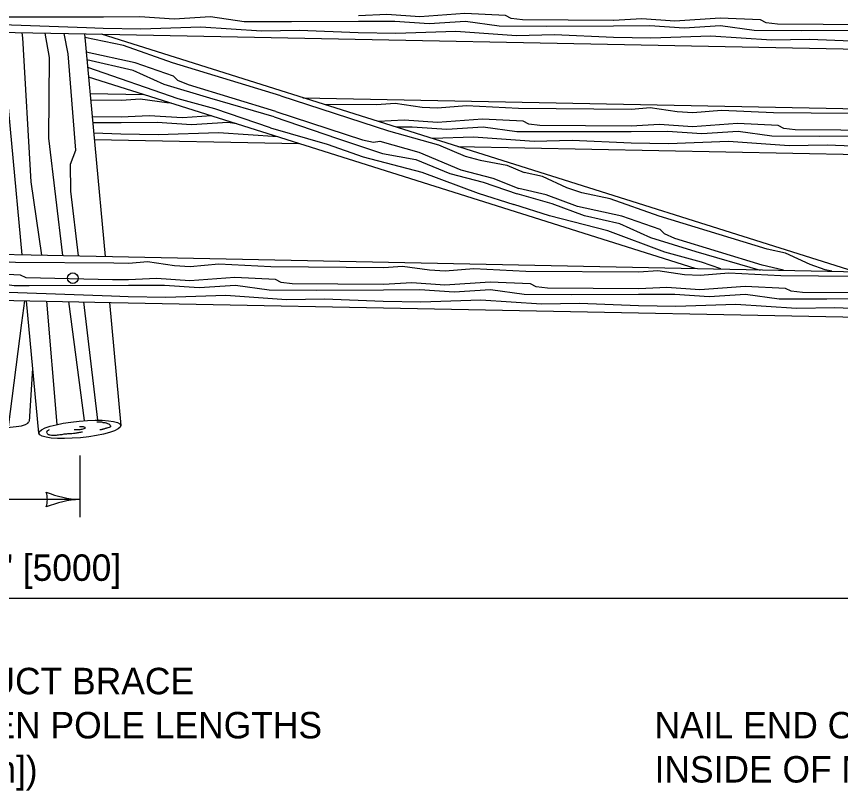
# Model space of a CAD drawing. Extents: x 49991.4 to 50021, y 49987.6 to 50011.4.
# Drawn here: x 50012.08 to 50013.947, y 49990.172 to 49991.926 of the extents above; entities that cross this region are included whole.
import ezdxf

# ---------------------------------------------------------------- set-up
doc = ezdxf.new("R2010")
doc.units = 0
for name, color, linetype in [('Level 1', 7, 'Continuous'), ('Level 2', 7, 'Continuous'), ('Level 3', 7, 'Continuous')]:
    doc.layers.add(name, color=color, linetype=linetype)

msp = doc.modelspace()

# ---------------------------------------------------------------- linework, layer by layer
at = {"layer": 'Level 1'}
for p, q in [((50009.7667, 49991.9345), (50012.238, 49991.8861)), ((50012.0454, 49991.8899), (50012.0923, 49991.3859)), ((50012.2344, 49991.8862), (50012.2813, 49991.3821)), ((50012.238, 49991.8861), (50014.3555, 49991.8446)), ((50013.9784, 49991.3477), (50012.273, 49991.8854)), ((50013.6177, 49991.355), (50012.2435, 49991.7883)), ((50012.2469, 49991.7514), (50012.3683, 49991.749)), ((50012.7289, 49991.7417), (50014.2392, 49991.7111)), ((50012.2566, 49991.6471), (50012.7202, 49991.638)), ((50013.0799, 49991.631), (50014.2673, 49991.6077)), ((50009.8311, 49991.4318), (50012.1135, 49991.3855)), ((50012.1135, 49991.3855), (50014.4188, 49991.3388)), ((50009.8234, 49991.3261), (50012.2947, 49991.2777)), ((50012.1021, 49991.2815), (50012.13, 49990.9817)), ((50012.291, 49991.2778), (50012.3169, 49990.999)), ((50012.2947, 49991.2777), (50014.4122, 49991.2362)), ((50012.1163, 49991.128), (50012.1087, 49991.0076))]:
    msp.add_line(p, q, dxfattribs=at)
for points in [[(50012.2773, 49991.9243), (50012.0522, 49991.9239)], [(50012.8552, 49991.9142), (50012.7035, 49991.9134), (50012.5958, 49991.914), (50012.5195, 49991.9246), (50012.4371, 49991.9194), (50012.3593, 49991.9246), (50012.2773, 49991.9243)], [(50013.4334, 49991.9168), (50013.2264, 49991.9185), (50013.201, 49991.9215), (50013.1883, 49991.9281), (50013.0964, 49991.9324), (50012.9941, 49991.9251), (50012.919, 49991.9302), (50012.8554, 49991.9269)], [(50012.2389, 49991.9), (50011.9199, 49991.9117), (50011.7837, 49991.9071), (50011.6989, 49991.9086)], [(50013.4331, 49991.9041), (50013.2814, 49991.9034), (50013.1737, 49991.904), (50013.0974, 49991.9145), (50013.0151, 49991.9093), (50012.9372, 49991.9145), (50012.8552, 49991.9142)], [(50014.011, 49991.8941), (50013.8594, 49991.8933), (50013.7516, 49991.8939), (50013.6754, 49991.9045), (50013.593, 49991.8992), (50013.5151, 49991.9045), (50013.4331, 49991.9041)], [(50014.0113, 49991.9068), (50013.8043, 49991.9084), (50013.7789, 49991.9114), (50013.7662, 49991.9181), (50013.6743, 49991.9223), (50013.572, 49991.915), (50013.497, 49991.9202), (50013.4333, 49991.9168)], [(50012.1376, 49991.385), (50012.1135, 49991.5509), (50012.0947, 49991.8774), (50012.0928, 49991.889)], [(50012.1853, 49991.3841), (50012.1532, 49991.65), (50012.1553, 49991.833), (50012.1448, 49991.8879)], [(50012.2204, 49991.3833), (50012.203, 49991.5302), (50012.2025, 49991.5911), (50012.2144, 49991.6228), (50012.1971, 49991.8408), (50012.1879, 49991.8871)], [(50012.2768, 49991.8985), (50012.2389, 49991.9)], [(50012.8547, 49991.8884), (50012.7216, 49991.8939), (50012.6351, 49991.8922), (50012.4978, 49991.9016), (50012.3616, 49991.897), (50012.2768, 49991.8985)], [(50013.4327, 49991.8784), (50013.2995, 49991.8838), (50013.213, 49991.8822), (50013.0757, 49991.8916), (50012.9395, 49991.8869), (50012.8547, 49991.8884)], [(50012.679, 49991.746), (50012.4336, 49991.8209), (50012.3225, 49991.86), (50012.2351, 49991.8783)], [(50014.0106, 49991.8683), (50013.8774, 49991.8737), (50013.7909, 49991.8721), (50013.6536, 49991.8815), (50013.5174, 49991.8769), (50013.4327, 49991.8784)], [(50012.6676, 49991.7102), (50012.4697, 49991.7705), (50012.4461, 49991.7806), (50012.436, 49991.7906), (50012.349, 49991.8207), (50012.2382, 49991.8452)], [(50012.6638, 49991.698), (50012.5182, 49991.7405), (50012.415, 49991.7716), (50012.3448, 49991.8033), (50012.2399, 49991.8273)], [(50012.656, 49991.6734), (50012.5299, 49991.7165), (50012.4466, 49991.7395), (50012.2415, 49991.8101)], [(50012.431, 49991.7292), (50012.4212, 49991.7297), (50012.3604, 49991.7385), (50012.318, 49991.7352)], [(50012.679, 49991.746), (50012.923, 49991.6666), (50013.0362, 49991.6349), (50013.0965, 49991.6092), (50013.1306, 49991.5998), (50013.1911, 49991.5888), (50013.2302, 49991.5722)], [(50012.3181, 49991.7352), (50012.2484, 49991.7358)], [(50012.896, 49991.7252), (50012.7782, 49991.7261)], [(50013.4739, 49991.7151), (50013.2173, 49991.7172), (50013.0998, 49991.7231), (50013.0345, 49991.7178), (50012.9991, 49991.7197), (50012.9383, 49991.7285), (50012.896, 49991.7252)], [(50014.0518, 49991.705), (50013.7953, 49991.7071), (50013.6777, 49991.713), (50013.6124, 49991.7077), (50013.5771, 49991.7096), (50013.5162, 49991.7184), (50013.4739, 49991.7151)], [(50012.5221, 49991.7005), (50012.456, 49991.6958), (50012.381, 49991.7009), (50012.3174, 49991.6976)], [(50012.6676, 49991.7102), (50012.8644, 49991.646), (50012.8894, 49991.6408), (50012.9035, 49991.6431), (50012.992, 49991.618), (50013.0868, 49991.5786), (50013.1596, 49991.5597), (50013.2188, 49991.5363)], [(50012.3174, 49991.6976), (50012.2519, 49991.6981)], [(50012.3172, 49991.6849), (50012.2531, 49991.6845)], [(50012.5793, 49991.6824), (50012.5594, 49991.6852), (50012.477, 49991.68), (50012.3992, 49991.6852), (50012.3172, 49991.6849)], [(50012.6638, 49991.698), (50012.8073, 49991.6492), (50012.9098, 49991.6156), (50012.9854, 49991.6014), (50013.0619, 49991.5703), (50013.1374, 49991.5505), (50013.215, 49991.5241)], [(50013.4733, 49991.6774), (50013.2663, 49991.679), (50013.2409, 49991.6821), (50013.2282, 49991.6887), (50013.1363, 49991.693), (50013.034, 49991.6857), (50012.9589, 49991.6908), (50012.8999, 49991.6877)], [(50014.0512, 49991.6673), (50013.8442, 49991.669), (50013.8188, 49991.672), (50013.8061, 49991.6786), (50013.7142, 49991.6829), (50013.6119, 49991.6756), (50013.5369, 49991.6807), (50013.4732, 49991.6774)], [(50012.3167, 49991.6591), (50012.2553, 49991.6616)], [(50012.6727, 49991.653), (50012.5377, 49991.6622), (50012.4015, 49991.6576), (50012.3167, 49991.6591)], [(50012.656, 49991.6734), (50012.784, 49991.6364), (50012.8656, 49991.6074), (50012.9988, 49991.5727), (50013.1265, 49991.5252), (50013.2073, 49991.4996)], [(50013.473, 49991.6647), (50013.3213, 49991.664), (50013.2136, 49991.6646), (50013.1373, 49991.6751), (50013.055, 49991.6699), (50012.9771, 49991.6751), (50012.9404, 49991.675)], [(50014.0509, 49991.6546), (50013.8993, 49991.6539), (50013.7915, 49991.6545), (50013.7153, 49991.665), (50013.6329, 49991.6598), (50013.555, 49991.665), (50013.473, 49991.6647)], [(50013.4726, 49991.6389), (50013.3394, 49991.6444), (50013.2529, 49991.6428), (50013.1156, 49991.6521), (50013.0228, 49991.649)], [(50014.0505, 49991.6289), (50013.9173, 49991.6343), (50013.8308, 49991.6327), (50013.6935, 49991.6421), (50013.5573, 49991.6375), (50013.4726, 49991.6389)], [(50013.7814, 49991.3985), (50013.5361, 49991.4733), (50013.425, 49991.5123), (50013.3609, 49991.5258), (50013.3275, 49991.5377), (50013.2717, 49991.5634), (50013.2302, 49991.5722)], [(50013.77, 49991.3625), (50013.5721, 49991.4229), (50013.5486, 49991.433), (50013.5383, 49991.443), (50013.4515, 49991.4732), (50013.3512, 49991.4952), (50013.2807, 49991.5215), (50013.2188, 49991.5363)], [(50013.7662, 49991.3504), (50013.6206, 49991.3928), (50013.5175, 49991.4239), (50013.4474, 49991.4557), (50013.3669, 49991.4741), (50013.2936, 49991.5012), (50013.215, 49991.5241)], [(50013.6764, 49991.3538), (50013.6324, 49991.3689), (50013.549, 49991.3919), (50013.42, 49991.4399), (50013.2882, 49991.4742), (50013.2073, 49991.4996)], [(50013.9279, 49991.3487), (50013.9122, 49991.352), (50013.8787, 49991.3638), (50013.8229, 49991.3896), (50013.7814, 49991.3985)], [(50012.3004, 49991.3666), (50012.0783, 49991.3683), (50011.9608, 49991.3742), (50011.8955, 49991.3689), (50011.8601, 49991.3708), (50011.7993, 49991.3796), (50011.7569, 49991.3763)], [(50012.3349, 49991.3663), (50012.3004, 49991.3666)], [(50012.9128, 49991.3562), (50012.6562, 49991.3583), (50012.5387, 49991.3641), (50012.4734, 49991.3588), (50012.438, 49991.3608), (50012.3772, 49991.3695), (50012.3348, 49991.3663)], [(50012.298, 49991.3289), (50012.1018, 49991.3332), (50012.0892, 49991.3399), (50011.9972, 49991.3441), (50011.8949, 49991.3369), (50011.8199, 49991.342), (50011.7562, 49991.3387)], [(50013.4907, 49991.3461), (50013.2341, 49991.3482), (50013.1166, 49991.3541), (50013.0513, 49991.3488), (50013.0159, 49991.3507), (50012.9551, 49991.3595), (50012.9127, 49991.3562)], [(50014.0686, 49991.336), (50013.8121, 49991.3381), (50013.6945, 49991.344), (50013.6292, 49991.3387), (50013.5938, 49991.3406), (50013.533, 49991.3494), (50013.4907, 49991.3461)], [(50013.8182, 49991.351), (50013.77, 49991.3625)], [(50012.1089, 49991.3155), (50012.0746, 49991.3157), (50011.9983, 49991.3263), (50011.9159, 49991.3211), (50011.838, 49991.3263), (50011.756, 49991.326)], [(50012.3342, 49991.3286), (50012.298, 49991.3289)], [(50012.9121, 49991.3185), (50012.7052, 49991.3201), (50012.6797, 49991.3232), (50012.6671, 49991.3298), (50012.5752, 49991.3341), (50012.4728, 49991.3268), (50012.3978, 49991.3319), (50012.3342, 49991.3286)], [(50012.334, 49991.3159), (50012.1089, 49991.3155)], [(50012.9119, 49991.3058), (50012.7602, 49991.3051), (50012.6525, 49991.3056), (50012.5762, 49991.3162), (50012.4938, 49991.311), (50012.4159, 49991.3162), (50012.334, 49991.3159)], [(50013.49, 49991.3084), (50013.2831, 49991.3101), (50013.2576, 49991.3131), (50013.245, 49991.3197), (50013.1531, 49991.324), (50013.0508, 49991.3167), (50012.9757, 49991.3218), (50012.9121, 49991.3185)], [(50014.068, 49991.2984), (50013.861, 49991.3), (50013.8356, 49991.303), (50013.8229, 49991.3097), (50013.731, 49991.3139), (50013.6287, 49991.3066), (50013.5536, 49991.3118), (50013.49, 49991.3084)], [(50012.2955, 49991.2917), (50011.9766, 49991.3033), (50011.8404, 49991.2987), (50011.7556, 49991.3002)], [(50012.3335, 49991.2901), (50012.2955, 49991.2917)], [(50012.9114, 49991.28), (50012.7783, 49991.2855), (50012.6918, 49991.2839), (50012.5545, 49991.2932), (50012.4183, 49991.2886), (50012.3335, 49991.2901)], [(50013.4898, 49991.2957), (50013.3381, 49991.295), (50013.2304, 49991.2956), (50013.1541, 49991.3061), (50013.0718, 49991.3009), (50012.9939, 49991.3061), (50012.9119, 49991.3058)], [(50014.0677, 49991.2857), (50013.9161, 49991.2849), (50013.8083, 49991.2855), (50013.7321, 49991.2961), (50013.6497, 49991.2908), (50013.5718, 49991.2961), (50013.4898, 49991.2957)], [(50012.0622, 49990.995), (50012.092, 49991.2313), (50012.099, 49991.2815)], [(50012.1724, 49991.0013), (50012.1487, 49991.2805)], [(50012.2345, 49991.01), (50012.1991, 49991.2796)], [(50012.2645, 49991.011), (50012.2328, 49991.2789)], [(50013.4894, 49991.27), (50013.3562, 49991.2754), (50013.2697, 49991.2738), (50013.1324, 49991.2832), (50012.9962, 49991.2785), (50012.9114, 49991.28)], [(50014.0673, 49991.2599), (50013.9341, 49991.2653), (50013.8476, 49991.2637), (50013.7103, 49991.2731), (50013.5741, 49991.2685), (50013.4894, 49991.27)]]:
    msp.add_lwpolyline(points, dxfattribs=at)
msp.add_circle((50012.2078, 49991.3328), 0.012, dxfattribs=at)
msp.add_ellipse((50012.0148, 49991.0138), major_axis=(-0.0937, 0.0061), ratio=0.194104, start_param=0.000064, end_param=3.132664, dxfattribs=at)
msp.add_ellipse((50012.2237, 49990.9901), major_axis=(0.0932, 0.0089), ratio=0.201992, dxfattribs=at)
for points in [[(50012.223, 49990.9965), (50012.2261, 49990.9969), (50012.2303, 49990.9965), (50012.2325, 49990.9962), (50012.2352, 49990.9947), (50012.2355, 49990.993), (50012.2329, 49990.9912), (50012.2285, 49990.9901), (50012.2236, 49990.9894), (50012.2201, 49990.9889), (50012.2147, 49990.9888), (50012.2119, 49990.9888), (50012.211, 49990.9888)], [(50012.2624, 49991.0071), (50012.267, 49991.0071), (50012.2715, 49991.0071), (50012.2747, 49991.0064), (50012.2777, 49991.0056), (50012.2825, 49991.005), (50012.2847, 49991.0041), (50012.2885, 49991.0029), (50012.2899, 49991.0021), (50012.2911, 49991.0009), (50012.2926, 49990.9994), (50012.2935, 49990.9972), (50012.2929, 49990.9962), (50012.2903, 49990.9947), (50012.2847, 49990.993), (50012.2829, 49990.9924), (50012.2762, 49990.9904), (50012.2738, 49990.9899), (50012.2707, 49990.9888), (50012.2693, 49990.9888)], [(50012.154, 49990.9888), (50012.1518, 49990.9878), (50012.1492, 49990.9857), (50012.1484, 49990.9835), (50012.1497, 49990.9813), (50012.151, 49990.9793), (50012.1534, 49990.9782), (50012.1566, 49990.9774), (50012.1625, 49990.9772), (50012.1707, 49990.9772), (50012.1755, 49990.978), (50012.1811, 49990.9785), (50012.1904, 49990.98), (50012.1988, 49990.9806), (50012.2055, 49990.9811), (50012.2128, 49990.9817), (50012.2218, 49990.9832), (50012.23, 49990.9845)]]:
    msp.add_spline(points, degree=3, dxfattribs=at)
at = {"layer": 'Level 3'}
for p, q in [((50012.2237, 49990.9311), (50012.2237, 49990.7911)), ((50012.2237, 49990.8311), (50009.9376, 49990.8311)), ((50014.532, 49990.6068), (50009.9376, 49990.6068))]:
    msp.add_line(p, q, dxfattribs=at)
for centre, radius, start, end in [((50012.2328, 49991.0533), 0.2223, 247.456, 267.6395), ((50012.0954, 49990.8311), 0.0548, 342.1388, 17.8612), ((50012.2351, 49990.5984), 0.233, 92.8273, 112.0772)]:
    msp.add_arc(centre, radius, start, end, dxfattribs=at)

# ---------------------------------------------------------------- texts
at = {"layer": 'Level 2'}
msp.add_text('16\'-6" [5000]', height=0.06, rotation=0, dxfattribs=at).set_placement((50011.8677, 49990.6468))
for s, p in [('CONSTRUCT BRACE', (50011.6802, 49990.3898)), ('EVERY TEN POLE LENGTHS ', (50011.6802, 49990.2898)), ('NAIL END OF POLE TO', (50013.526, 49990.2898)), ("(180' [55 m])", (50011.6802, 49990.1898)), ('INSIDE OF NEAR JACK LEG.', (50013.526, 49990.1898))]:
    msp.add_text(s, height=0.06, dxfattribs=at).set_placement(p)

doc.saveas('drawing.dxf')
